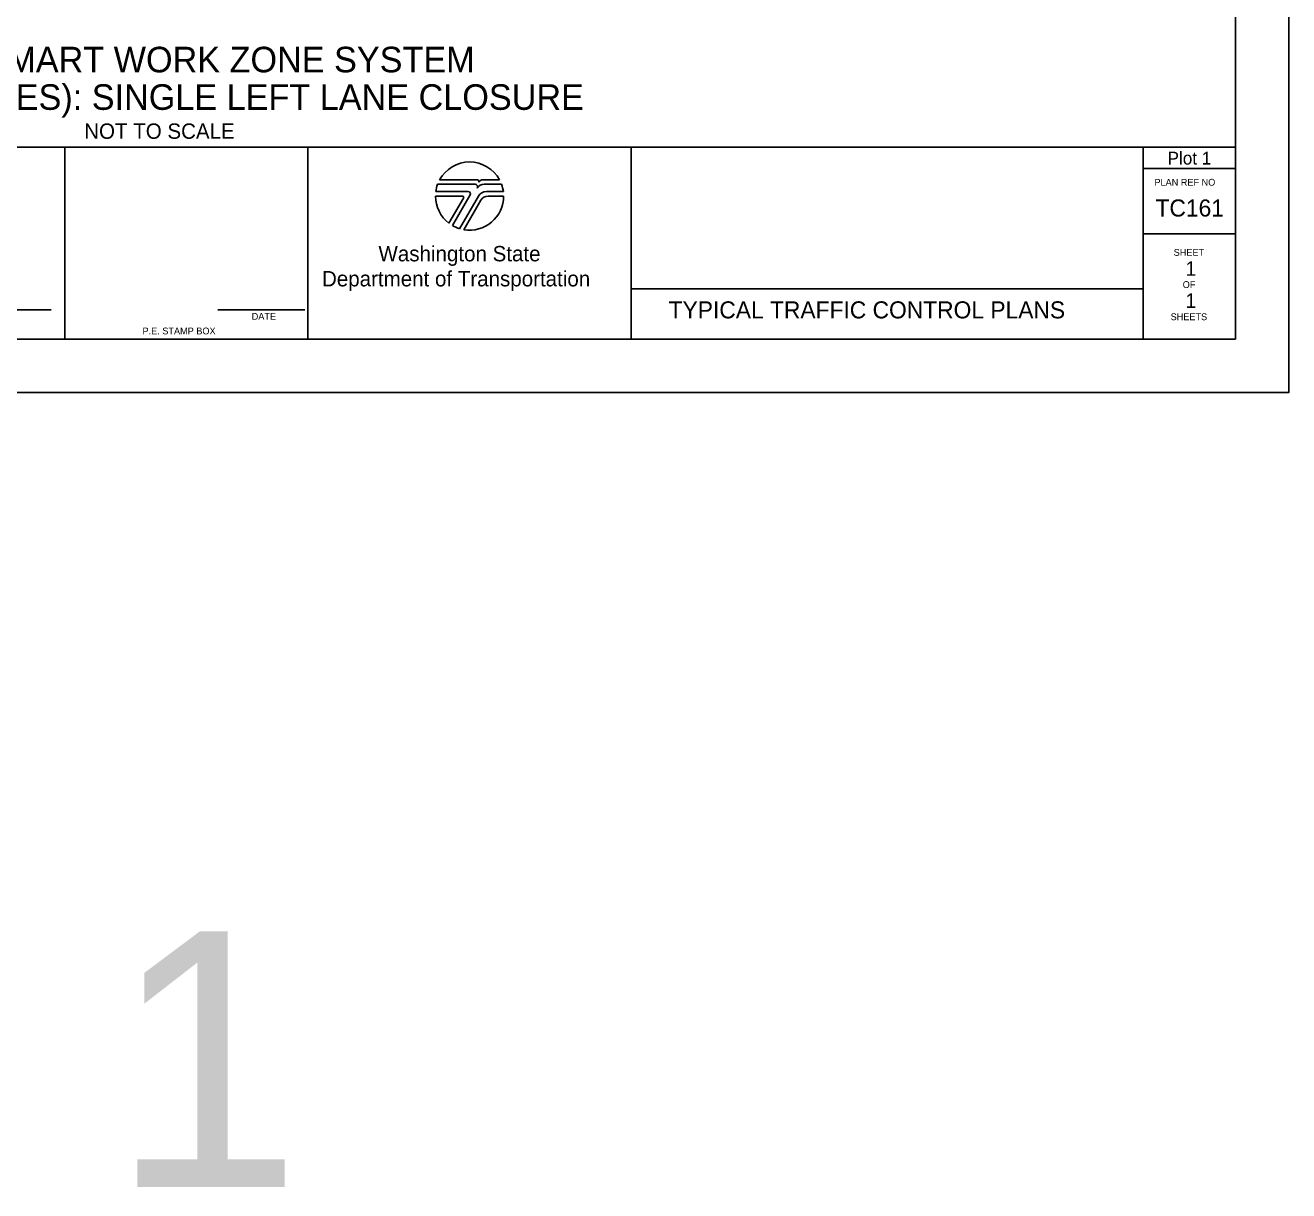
# Model space of a CAD drawing. Extents: x 99999.1 to 100035.7, y 99995 to 100010.7.
# Drawn here: x 100008.65 to 100016.06, y 99995.01 to 100001.84 of the extents above; entities that cross this region are included whole.
import ezdxf

# ---------------------------------------------------------------- set-up
doc = ezdxf.new("R2010")
doc.units = 0
for name, color, linetype in [('SH_DE_DetailHeading1Text', 7, 'Continuous'), ('SH_DE_DetailHeading3Text', 7, 'Continuous'), ('SH_GI_PlotLimits', 7, 'Continuous'), ('SH_GI_SheetBorder', 7, 'Continuous'), ('SH_GI_SheetLocationText', 7, 'Continuous'), ('SH_GI_SheetTextInCells', 7, 'Continuous'), ('SH_GI_TitleBlockText', 7, 'Continuous'), ('SH_GI_WSDOTLogo', 7, 'Continuous')]:
    doc.layers.add(name, color=color, linetype=linetype)

msp = doc.modelspace()

# ---------------------------------------------------------------- linework, layer by layer
at = {"layer": 'SH_GI_PlotLimits'}
msp.add_lwpolyline([(99999.0625, 99999.6875), (100016.0625, 99999.6875), (100016.0625, 100010.6875), (99999.0625, 100010.6875)], close=True, dxfattribs=at)
at = {"layer": 'SH_GI_SheetBorder'}
for p, q in [((100015.75, 100010.375), (100015.75, 100000)), ((100000, 100001.1259), (100015.75, 100001.1259)), ((100008.8828, 100000), (100008.8828, 100001.1259)), ((100010.3089, 100001.1259), (100010.3089, 100000)), ((100012.2055, 100001.1259), (100012.2055, 100000)), ((100015.2079, 100001.1259), (100015.2079, 100000)), ((100015.2079, 100001.0008), (100015.75, 100001.0008)), ((100015.2079, 100000.6176), (100015.75, 100000.6176)), ((100012.2055, 100000.2955), (100015.2079, 100000.2955)), ((100008.2903, 100000.1733), (100008.802, 100000.1733)), ((100009.7797, 100000.1733), (100010.2914, 100000.1733)), ((100000, 100000), (100015.75, 100000))]:
    msp.add_line(p, q, dxfattribs=at)
at = {"layer": 'SH_GI_WSDOTLogo'}
for p, q in [((100011.2894, 100000.9094), (100011.0697, 100000.9094)), ((100011.303, 100000.9354), (100011.0815, 100000.9354)), ((100011.433, 100000.9354), (100011.3351, 100000.9354)), ((100011.343, 100000.9094), (100011.3429, 100000.9094)), ((100011.4448, 100000.9094), (100011.343, 100000.9094)), ((100011.0572, 100000.84), (100011.2148, 100000.84)), ((100011.059, 100000.8661), (100011.2496, 100000.8661)), ((100011.222, 100000.8277), (100011.1364, 100000.6807)), ((100011.261, 100000.8464), (100011.1567, 100000.6672)), ((100011.1989, 100000.6487), (100011.3089, 100000.839)), ((100011.3558, 100000.8661), (100011.4555, 100000.8661)), ((100011.3655, 100000.8394), (100011.4572, 100000.8394)), ((100011.2244, 100000.6428), (100011.3242, 100000.8156))]:
    msp.add_line(p, q, dxfattribs=at)
for centre, radius, start, end in [((100011.2572, 100000.84), 0.2, 28.47865, 151.53204), ((100011.2572, 100000.84), 0.2, 159.69598, 172.50569), ((100011.2894, 100000.8946), 0.0148, 327.8418, 89.99855), ((100011.3429, 100000.861), 0.0484, 89.99529, 147.82376), ((100011.303, 100000.9263), 0.00903, 329.87418, 90.00328), ((100011.3352, 100000.9066), 0.0287, 90.00721, 148.16763), ((100011.2572, 100000.84), 0.2, 7.49431, 20.29406), ((100011.2572, 100000.84), 0.2, 179.99864, 232.84327), ((100011.2149, 100000.8318), 0.0082, 329.74356, 90), ((100011.2572, 100000.84), 0.2, 260.54554, 359.80857), ((100011.2497, 100000.853), 0.0131, 329.76834, 90), ((100011.3558, 100000.8119), 0.0542, 90, 149.99738), ((100011.3654, 100000.7918), 0.0476, 90, 150.05432), ((100011.2572, 100000.84), 0.2, 239.79292, 253.0448)]:
    msp.add_arc(centre, radius, start, end, dxfattribs=at)

# ---------------------------------------------------------------- texts
at = {"layer": 'SH_DE_DetailHeading1Text'}
for s, p in [('6-MILE SMART WORK ZONE SYSTEM', (100007.7097, 100001.5658)), ('FREEWAY (2 LANES): SINGLE LEFT LANE CLOSURE', (100006.9232, 100001.3458))]:
    msp.add_text(s, height=0.15, dxfattribs=at).set_placement(p)
at = {"layer": 'SH_DE_DetailHeading3Text'}
msp.add_text('NOT TO SCALE', height=0.09, dxfattribs=at).set_placement((100008.9969, 100001.1759))
at = {"layer": 'SH_GI_SheetBorder'}
msp.add_text('PLAN REF NO', height=0.040032, dxfattribs=at).set_placement((100015.2747, 100000.9008))
at = {"layer": 'SH_GI_SheetLocationText'}
for height, p in [(0.075, (100015.3518, 100001.025)), (1.5, (100005.1422, 99995.0267))]:
    msp.add_text('Plot 1', height=height, dxfattribs=at).set_placement(p)
at = {"layer": 'SH_GI_SheetTextInCells'}
for s, height, p in [('Washington State', 0.090072, (100010.7229, 100000.4571)), ('SHEET', 0.04003, (100015.3877, 100000.4896)), ('Department of Transportation', 0.090072, (100010.3916, 100000.3101)), ('OF', 0.04003, (100015.4406, 100000.3008)), ('DATE', 0.04003, (100009.9794, 100000.1141)), ('SHEETS', 0.04003, (100015.3698, 100000.112)), ('P.E. STAMP BOX', 0.040032, (100009.339, 100000.0286))]:
    msp.add_text(s, height=height, dxfattribs=at).set_placement(p)
at = {"layer": 'SH_GI_TitleBlockText'}
for s, height, p in [('TC161', 0.1, (100015.2811, 100000.72)), ('1', 0.085, (100015.4566, 100000.3723)), ('TYPICAL TRAFFIC CONTROL PLANS', 0.1, (100012.4251, 100000.1224)), ('1', 0.085, (100015.4566, 100000.1843))]:
    msp.add_text(s, height=height, dxfattribs=at).set_placement(p)

doc.saveas('drawing.dxf')
